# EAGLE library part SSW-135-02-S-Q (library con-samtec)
THROUGH-HOLE .025" SQ POST SOCKET Source: Samtec SSW.pdf
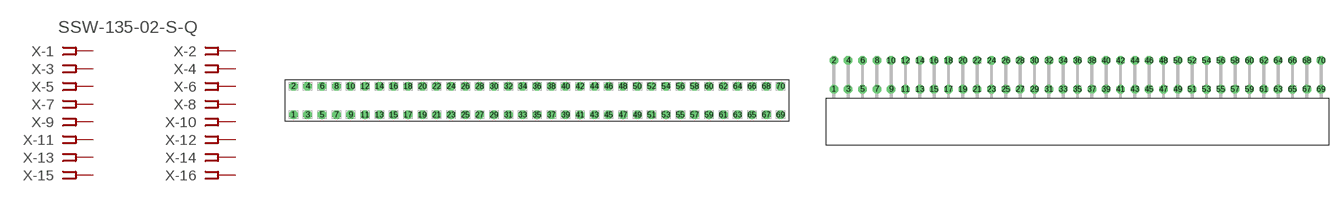
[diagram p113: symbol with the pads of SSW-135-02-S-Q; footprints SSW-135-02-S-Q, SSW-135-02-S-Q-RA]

Designator prefix X; gates -1=FPINV -2=FPIN -3=FPIN -4=FPIN -5=FPIN -6=FPIN -7=FPIN -8=FPIN -9=FPIN -10=FPIN -11=FPIN -12=FPIN -13=FPIN -14=FPIN -15=FPIN -16=FPIN -17=FPIN -18=FPIN -19=FPIN -20=FPIN -21=FPIN -22=FPIN -23=FPIN -24=FPIN -25=FPIN -26=FPIN -27=FPIN -28=FPIN -29=FPIN -30=FPIN -31=FPIN -32=FPIN -33=FPIN -34=FPIN -35=FPIN -36=FPIN -37=FPIN -38=FPIN -39=FPIN -40=FPIN -41=FPIN -42=FPIN -43=FPIN -44=FPIN -45=FPIN -46=FPIN -47=FPIN -48=FPIN -49=FPIN -50=FPIN -51=FPIN -52=FPIN -53=FPIN -54=FPIN -55=FPIN -56=FPIN -57=FPIN -58=FPIN -59=FPIN -60=FPIN -61=FPIN -62=FPIN -63=FPIN -64=FPIN -65=FPIN -66=FPIN -67=FPIN -68=FPIN -69=FPIN -70=FPIN

## SSW-135-02-S-Q (MPN: SSW-135-02-S-Q; OC_FARNELL: unknown; OC_NEWARK: 83P0776)  [SSW-135-02-S-Q]
1  -1:1  pas
2  -2:1  pas
3  -3:1  pas
4  -4:1  pas
5  -5:1  pas
6  -6:1  pas
7  -7:1  pas
8  -8:1  pas
9  -9:1  pas
10  -10:1  pas
11  -11:1  pas
12  -12:1  pas
13  -13:1  pas
14  -14:1  pas
15  -15:1  pas
16  -16:1  pas
17  -17:1  pas
18  -18:1  pas
19  -19:1  pas
20  -20:1  pas
21  -21:1  pas
22  -22:1  pas
23  -23:1  pas
24  -24:1  pas
25  -25:1  pas
26  -26:1  pas
27  -27:1  pas
28  -28:1  pas
29  -29:1  pas
30  -30:1  pas
31  -31:1  pas
32  -32:1  pas
33  -33:1  pas
34  -34:1  pas
35  -35:1  pas
36  -36:1  pas
37  -37:1  pas
38  -38:1  pas
39  -39:1  pas
40  -40:1  pas
41  -41:1  pas
42  -42:1  pas
43  -43:1  pas
44  -44:1  pas
45  -45:1  pas
46  -46:1  pas
47  -47:1  pas
48  -48:1  pas
49  -49:1  pas
50  -50:1  pas
51  -51:1  pas
52  -52:1  pas
53  -53:1  pas
54  -54:1  pas
55  -55:1  pas
56  -56:1  pas
57  -57:1  pas
58  -58:1  pas
59  -59:1  pas
60  -60:1  pas
61  -61:1  pas
62  -62:1  pas
63  -63:1  pas
64  -64:1  pas
65  -65:1  pas
66  -66:1  pas
67  -67:1  pas
68  -68:1  pas
69  -69:1  pas
70  -70:1  pas

## SSW-135-02-S-QRA (MPN: SSW-135-02-S-Q-RA; OC_FARNELL: unknown; OC_NEWARK: 83P0777)  [SSW-135-02-S-Q-RA]
Pads as for SSW-135-02-S-Q

## Footprint SSW-135-02-S-Q (pad centres in mm)
THROUGH-HOLE .025" SQ POST SOCKET Source: Samtec SSW.pdf
drill 1 pad 1.5 octagon: 1 -43.18,-2.54; 2 -43.18,2.54; 3 -40.64,-2.54; 4 -40.64,2.54; 5 -38.1,-2.54; 6 -38.1,2.54; 7 -35.56,-2.54; 8 -35.56,2.54; 9 -33.02,-2.54; 10 -33.02,2.54; 11 -30.48,-2.54; 12 -30.48,2.54; 13 -27.94,-2.54; 14 -27.94,2.54; 15 -25.4,-2.54; 16 -25.4,2.54; 17 -22.86,-2.54; 18 -22.86,2.54; 19 -20.32,-2.54; 20 -20.32,2.54; 21 -17.78,-2.54; 22 -17.78,2.54; 23 -15.24,-2.54; 24 -15.24,2.54; 25 -12.7,-2.54; 26 -12.7,2.54; 27 -10.16,-2.54; 28 -10.16,2.54; 29 -7.62,-2.54; 30 -7.62,2.54; 31 -5.08,-2.54; 32 -5.08,2.54; 33 -2.54,-2.54; 34 -2.54,2.54; 35 0,-2.54; 36 0,2.54; 37 2.54,-2.54; 38 2.54,2.54; 39 5.08,-2.54; 40 5.08,2.54; 41 7.62,-2.54; 42 7.62,2.54; 43 10.16,-2.54; 44 10.16,2.54; 45 12.7,-2.54; 46 12.7,2.54; 47 15.24,-2.54; 48 15.24,2.54; 49 17.78,-2.54; 50 17.78,2.54; 51 20.32,-2.54; 52 20.32,2.54; 53 22.86,-2.54; 54 22.86,2.54; 55 25.4,-2.54; 56 25.4,2.54; 57 27.94,-2.54; 58 27.94,2.54; 59 30.48,-2.54; 60 30.48,2.54; 61 33.02,-2.54; 62 33.02,2.54; 63 35.56,-2.54; 64 35.56,2.54; 65 38.1,-2.54; 66 38.1,2.54; 67 40.64,-2.54; 68 40.64,2.54; 69 43.18,-2.54; 70 43.18,2.54

## Footprint SSW-135-02-S-Q-RA (pad centres in mm)
THROUGH-HOLE .025" SQ POST SOCKET Source: Samtec SSW.pdf
drill 1 pad 1.5 octagon: 1 -43.18,1.524; 2 -43.18,6.604; 3 -40.64,1.524; 4 -40.64,6.604; 5 -38.1,1.524; 6 -38.1,6.604; 7 -35.56,1.524; 8 -35.56,6.604; 9 -33.02,1.524; 10 -33.02,6.604; 11 -30.48,1.524; 12 -30.48,6.604; 13 -27.94,1.524; 14 -27.94,6.604; 15 -25.4,1.524; 16 -25.4,6.604; 17 -22.86,1.524; 18 -22.86,6.604; 19 -20.32,1.524; 20 -20.32,6.604; 21 -17.78,1.524; 22 -17.78,6.604; 23 -15.24,1.524; 24 -15.24,6.604; 25 -12.7,1.524; 26 -12.7,6.604; 27 -10.16,1.524; 28 -10.16,6.604; 29 -7.62,1.524; 30 -7.62,6.604; 31 -5.08,1.524; 32 -5.08,6.604; 33 -2.54,1.524; 34 -2.54,6.604; 35 0,1.524; 36 0,6.604; 37 2.54,1.524; 38 2.54,6.604; 39 5.08,1.524; 40 5.08,6.604; 41 7.62,1.524; 42 7.62,6.604; 43 10.16,1.524; 44 10.16,6.604; 45 12.7,1.524; 46 12.7,6.604; 47 15.24,1.524; 48 15.24,6.604; 49 17.78,1.524; 50 17.78,6.604; 51 20.32,1.524; 52 20.32,6.604; 53 22.86,1.524; 54 22.86,6.604; 55 25.4,1.524; 56 25.4,6.604; 57 27.94,1.524; 58 27.94,6.604; 59 30.48,1.524; 60 30.48,6.604; 61 33.02,1.524; 62 33.02,6.604; 63 35.56,1.524; 64 35.56,6.604; 65 38.1,1.524; 66 38.1,6.604; 67 40.64,1.524; 68 40.64,6.604; 69 43.18,1.524; 70 43.18,6.604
